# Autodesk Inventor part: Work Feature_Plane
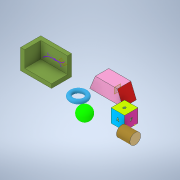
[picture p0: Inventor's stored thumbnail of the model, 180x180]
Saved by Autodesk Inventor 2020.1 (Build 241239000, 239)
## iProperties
Created: 2018-06
Part Number: Work Feature_Plane
Material: Generic
Document SubType Name: Modeling
Designer: Power User
Density: 1 g/cm^3
Appearance: Default
Author: Power User
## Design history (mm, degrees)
sketch "Sketch1"
  geometry: L1 (0, 0)-(50, 0); L2 (50, 0)-(50, -50); L3 (50, -50)-(0, -50); L4 (0, -50)-(0, 0); 1 further point
  constraints: 8 end point, 2 parallel, 1 coincident, 1 horizontal, 1 perpendicular
  dimensions: "d0" = 50 distance of L1.end L2.end; "d1" = 50 distance of L2.end L3.end; "d53" = 0 distance from line of point (0, 0) L4
extrude "Extrusion1" new body sketch "Sketch1" distance "d2" = 50; taper "d3" = 0 deg
workplane "Work Plane1"
sketch "Sketch2"
  geometry: L1 (0, 50)-(50, 50) reference; L2 (50, 0)-(50, 50) reference; C1 r 20 at (-30, 25); 3 further points
  constraints: 2 midpoint, 1 centre point, 1 horizontal alignment
  dimensions: "d5" = 40 diameter of C1; "d54" = 30 horizontal distance of C1.centre point (0, 0)
extrude "Extrusion2" new body sketch "Sketch2" distance "d6" = 50; taper "d7" = 0 deg
sketch "Sketch3"
  geometry: L1 (-172.16, 49.98)-(-172.16, 11.482); C1 r 7.5 at (-197.16, 26.587); 1 further point
  constraints: 2 end point, 1 centre point, 1 vertical
  dimensions: "d8" = 15 diameter of C1; "d9" = 50 diameter of C1.centre L1
revolve "Revolution1" sketch "Sketch3" stored, may be unused: angle "d10" = 90 deg
workplane "Work Plane2"
sketch "Sketch4"
  geometry: L1 (-98.807, 58.325)-(-98.807, 8.325); A1 r 25 centre (-98.807, 33.325) between (-98.807, 58.325) and (-98.807, 8.325); 1 further point
  constraints: 2 end point, 2 point on circle, 1 centre point, 1 vertical
  dimensions: "d12" = 50 diameter of A1
revolve "Revolution2" sketch "Sketch4" stored, may be unused: angle "d13" = 90 deg
workplane "Work Plane3"
sketch "Sketch5"
  geometry: L1 (-192.037, 9.98)-(-171.326, 59.98); L2 (-171.326, 59.98)-(-89.041, 59.98); L3 (-89.041, 59.98)-(-68.33, 9.98); L4 (-68.33, 9.98)-(-192.037, 9.98); L5 (-130.184, 59.98)-(-130.184, 9.98); 1 further point
  constraints: 10 end point, 2 midpoint, 1 horizontal, 1 parallel, 1 perpendicular, 1 other
  dimensions: "d15" = 50 distance between parallel lines of L4 L2; "d16" = 45 deg angle of L3 L1
extrude "Extrusion3" new body sketch "Sketch5" stored distance "d17" = 50; taper "d18" = 0 deg
sketch "Sketch6"
  geometry: L1 (15, 35)-(35, 35); L2 (35, 35)-(35, 15); L3 (35, 15)-(15, 15); L4 (15, 15)-(15, 35); L5 (0, 50)-(50, 50) reference; L6 (0, 0)-(0, 50) reference; 5 further points
  constraints: 4 midpoint, 1 horizontal alignment, 1 vertical alignment, 2 other
  dimensions: "d19" = 20 distance of L1.start L1.end; "d20" = 20 distance of L1.end L2.end
emboss "Emboss1" sketch "Sketch6" dims "d21" = 0.2, "d22" = 0
sketch "Sketch7"
  geometry: L1 (-35, 35)-(-15, 35); L2 (-15, 35)-(-15, 15); L3 (-15, 15)-(-35, 15); L4 (-35, 15)-(-35, 35); L5 (0, 50)-(-50, 50) reference; L6 (-50, 50)-(-50, 0) reference; 5 further points
  constraints: 4 midpoint, 1 horizontal alignment, 1 vertical alignment, 2 other
  dimensions: "d23" = 20 distance of L1.start L1.end; "d24" = 20 distance of L3.end L1.start
emboss "Emboss2" sketch "Sketch7" dims "d25" = 0.2, "d26" = 0
sketch "Sketch8"
  geometry: L1 (15, 35)-(35, 35); L2 (35, 35)-(35, 15); L3 (35, 15)-(15, 15); L4 (15, 15)-(15, 35); L5 (0, 0)-(0, 50) reference; L6 (0, 50)-(50, 50) reference; 4 further points
  constraints: 4 midpoint, 1 horizontal alignment, 1 vertical alignment, 2 other
  dimensions: "d27" = 20 distance of L1.start L1.end; "d28" = 20 distance of L3.end L1.start
emboss "Emboss3" sketch "Sketch8" dims "d29" = 0.2, "d30" = 0
sketch "Sketch9"
  geometry: L1 (-11.219, -35.018)-(-35.694, -35.018); L2 (-35.694, -35.018)-(-35.694, -14.982); L3 (-35.694, -14.982)-(-11.219, -14.982); L4 (-11.219, -14.982)-(-11.219, -35.018); L5 (0, -50)-(0, 0) reference; 4 further points
  constraints: 3 midpoint, 1 horizontal alignment, 1 vertical alignment, 2 other
emboss "Emboss4" sketch "Sketch9" dims "d31" = 0.2, "d32" = 0
sketch "Sketch10"
  geometry: L1 (15, 35)-(35, 35); L2 (35, 35)-(35, 15); L3 (35, 15)-(15, 15); L4 (15, 15)-(15, 35); L5 (0, 50)-(50, 50) reference; L6 (0, 0)-(0, 50) reference; 5 further points
  constraints: 4 midpoint, 1 horizontal alignment, 1 vertical alignment, 2 other
  dimensions: "d33" = 20 distance of L1.start L1.end; "d34" = 20 distance of L3.end L1.start
emboss "Emboss5" sketch "Sketch10" dims "d35" = 0.2, "d36" = 0
sketch "Sketch11"
  geometry: L1 (15, 35)-(35, 35); L2 (35, 35)-(35, 15); L3 (35, 15)-(15, 15); L4 (15, 15)-(15, 35); L5 (0, 0)-(0, 50) reference; L6 (0, 50)-(50, 50) reference; 4 further points
  constraints: 4 midpoint, 1 horizontal alignment, 1 vertical alignment, 2 other
  dimensions: "d37" = 20 distance of L1.start L1.end; "d38" = 20 distance of L1.end L2.end
emboss "Emboss6" sketch "Sketch11" dims "d39" = 0.2, "d40" = 0
sketch "Sketch12"
  geometry: L1 (118.439, 97.246)-(43.439, 97.246); L2 (43.439, 97.246)-(43.439, 172.246); L3 (43.439, 172.246)-(58.439, 172.246); L4 (58.439, 172.246)-(58.439, 112.246); L5 (58.439, 112.246)-(118.439, 112.246); L6 (118.439, 112.246)-(118.439, 97.246); 1 further point
  constraints: 12 end point, 4 perpendicular, 1 horizontal, 1 vertical
  dimensions: "d41" = 75 distance of L1.start L1.end; "d42" = 75 distance of L1.end L2.end (= d41); "d43" = 15 distance of L5.end L1.start; "d44" = 15 distance of L2.end L3.end (= d43)
extrude "Extrusion4" new body sketch "Sketch12" stored distance "d45" = 100; taper "d46" = 0 deg
sketch "Sketch13"
  geometry: L1 (97.246, 118.439)-(97.246, 43.439) reference; L2 (97.246, 43.439)-(172.246, 43.439) reference; L3 (172.246, 43.439)-(97.246, 43.439) reference; L4 (172.246, 118.439)-(97.246, 118.439); L5 (97.246, 118.439)-(97.246, 43.439); L6 (97.246, 43.439)-(172.246, 43.439); L7 (172.246, 43.439)-(172.246, 118.439); L8 (172.246, 118.439)-(97.246, 43.439); L9 (97.246, 118.439)-(172.246, 43.439); 2 further points
  constraints: 12 end point, 2 equal length, 2 midpoint, 2 parallel, 1 horizontal, 1 perpendicular
extrude "Extrusion5" join sketch "Sketch13" distance "d47" = 15; taper "d48" = 0 deg
feature "Move Body1"
workplane "Work Plane4"
workplane "Work Plane5"
workplane "Work Plane6"
workplane "Work Plane7"
workplane "Work Plane8"
workplane "Work Plane9"
workplane "Work Plane10"
workplane "Work Plane11"
workplane "Work Plane12"
workplane "Work Plane13"
workplane "Work Plane14"
workplane "Work Plane15"
workplane "Work Plane16"
sketch "Sketch14"
  geometry: L1 (0, 0)-(-10, 17.321); L2 (0, 0)-(-20, 0); C1 r 20 at (0, 0) reference; A1 r 20 centre (0, 0) between (-10, 17.321) and (-20, 0) reference; 1 further point
  constraints: 4 end point, 2 point on circle, 1 horizontal
  dimensions: "d58" = 60 deg angle of L1 L2
workplane "Work Plane17"
workplane "Work Plane18"
workplane "Work Plane19"
sketch "Sketch15"
  geometry: L1 (-92.268, 9.312)-(-70.537, 31.805); L2 (-70.537, 31.805)-(-44.104, 25.832); L3 (-44.104, 25.832)-(-23.517, 16.81); L4 (-23.517, 16.81)-(-11.699, 37.27); 1 further point
  constraints: 3 other
workplane "Work Plane20"
node "Cube"
node "Cylinder"
node "Ring"
node "Sphere"
node "Trapezoid"
node "Solid"
other parameters: "d14" = -87.5, "d56" = -15, "d57" = -30 deg
